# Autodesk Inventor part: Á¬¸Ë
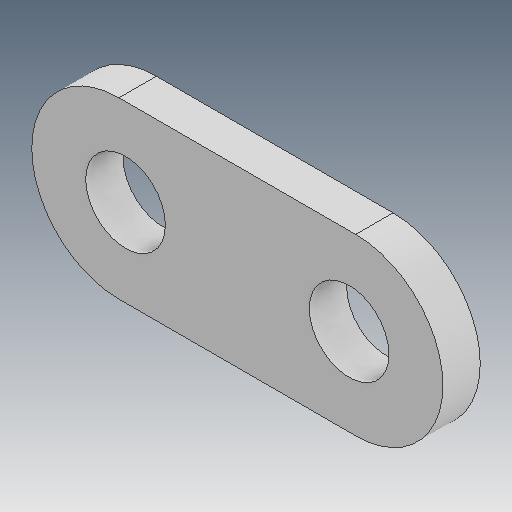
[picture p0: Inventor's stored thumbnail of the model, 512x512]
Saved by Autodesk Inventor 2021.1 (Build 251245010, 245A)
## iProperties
Created: 2020-03
Part Number: Á¬¸Ë
Material: Ogólny
Document SubType Name: Modeling
Designer: user
Density: 1 g/cm^3
Appearance: Domyślna
Author: user
Revision Number: ÈÎºÎ
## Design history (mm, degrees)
feature "Í¹Ì¨-À­Éì1"
node "Bryła1"
